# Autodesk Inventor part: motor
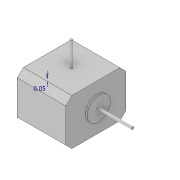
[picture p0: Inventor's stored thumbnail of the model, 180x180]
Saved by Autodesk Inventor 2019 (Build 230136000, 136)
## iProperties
Created: 2020-02
Part Number: motor
Material: Generic
Document SubType Name: Modeling
Designer: Krupashree
Density: 1 g/cm^3
Appearance: Default
Author: Krupashree
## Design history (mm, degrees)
sketch "Sketch1"
  geometry: L1 (7.893, 12.753)-(-1.607, 12.753); L2 (-1.607, 12.753)-(-1.607, 0.337); L3 (-1.607, 0.337)-(7.893, 0.337); L4 (7.893, 0.337)-(7.893, 12.753); 1 further point
  constraints: 8 end point, 2 parallel, 1 horizontal, 1 perpendicular
  dimensions: "d0" = 9.5 distance of L3.end L2.end
extrude "Extrusion1" new body sketch "Sketch1" distance "d1" = 10; taper "d2" = 0 deg
chamfer "Chamfer1" distance "d3" = 1.25; stored, may be unused: second distance "d4" = 1.25, angle "d5" = 45 deg
chamfer "Chamfer2" distance "d6" = 1.25; stored, may be unused: second distance "d7" = 1.25, angle "d8" = 45 deg
sketch "Sketch2"
  geometry: C1 r 2.393 at (-6.256, 3.08); 1 further point
  constraints: 1 centre point
extrude "Extrusion2" join sketch "Sketch2" distance "d9" = 0.3; taper "d10" = 0 deg
sketch "Sketch3"
  geometry: C1 r 0.25 at (0, 0); 1 further point
  constraints: 1 centre point
  dimensions: "d11" = 0.5 diameter of C1
extrude "Extrusion3" join sketch "Sketch3" distance "d12" = 7; taper "d13" = 0 deg
sketch "Sketch4"
  geometry: 1 further point
workplane "Work Plane1"
sketch "Sketch5"
  geometry: L1 (0.35, 6.674)-(12.807, -0.357); L2 (0.337, -0.357)-(12.807, 6.674); C1 r 0.25 at (6.572, 3.158); 1 further point
  constraints: 4 end point, 1 centre point, 1 midpoint
  dimensions: "d15" = 0.5 diameter of C1
workplane "Work Plane2"
sketch "Sketch6"
  geometry: L1 (0, 0)-(10, 0) reference; L2 (0, 9.941)-(10, 0); L3 (10, 9.917)-(0, 9.917) reference; L4 (10, 9.917)-(0, -0.059); C1 r 0.25 at (5, 4.929); 1 further point
  constraints: 4 end point, 1 centre point, 1 midpoint
  dimensions: "d17" = 0.5 diameter of C1
extrude "Extrusion4" join sketch "Sketch6" distance "d18" = 5; taper "d19" = 0 deg
body "Solid1"
other parameters: "d14" = 0, "d16" = 0
